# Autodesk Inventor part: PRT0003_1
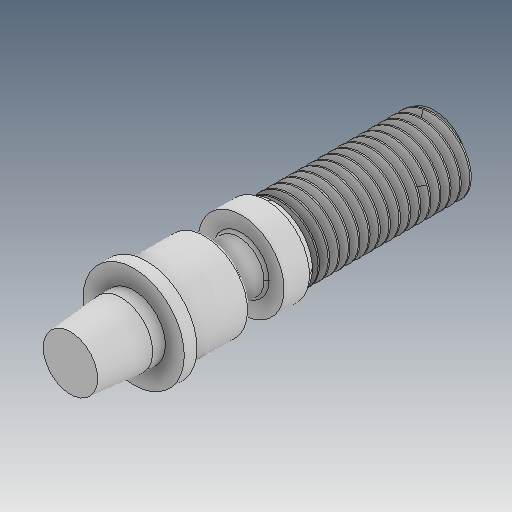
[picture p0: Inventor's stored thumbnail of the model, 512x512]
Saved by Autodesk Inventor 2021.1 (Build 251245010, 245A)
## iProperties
Created: 2019-04
Part Number: PRT0003_1
Material: Ogólny
Document SubType Name: Modeling
Designer: user
Density: 1 g/cm^3
Appearance: Domyślna
Author: user
Revision Number: ÈÎºÎ
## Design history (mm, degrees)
feature "ÊäÈë1"
node "Bryła1"
